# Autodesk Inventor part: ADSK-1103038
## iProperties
Shininess: 41.0
Length Units: 11272
Angle Units: 11279
Time Units: 11290
Mass Units: 11286
Length Display Precision: 4
Angle Display Precision: 2
Compacted: True
Created: 2000-08
Part Number: ADSK-1103038
Document SubType Name: Modeling
Description: METAL TIE
Mass: 0.127833 g
Surface Area: 3.35412 cm^2
Volume: 0.113127 cm^3
Density: 1.13 g/cm^3
Material: Nylon-6/6
Density: 0.0
Volumn: 0.0
Area: 0.0
PropertySet Name: Model Information
Control State: 0
Master: False
Checked Out: False
Author: Autodesk, Inc.
